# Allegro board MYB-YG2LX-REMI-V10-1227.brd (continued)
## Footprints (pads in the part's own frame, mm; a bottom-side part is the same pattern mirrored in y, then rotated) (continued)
TSSOP16
  oval 1.6x0.27 smd: 1(-2.9,2.275) 2(-2.9,1.625) 3(-2.9,0.975) 4(-2.9,0.325) 5(-2.9,-0.325) 6(-2.9,-0.975) 7(-2.9,-1.625) 8(-2.9,-2.275) 9(2.9,-2.275) 10(2.9,-1.625) 11(2.9,-0.975) 12(2.9,-0.325) 13(2.9,0.325) 14(2.9,0.975) 15(2.9,1.625) 16(2.9,2.275)
TSSOP20
  oval 1.5x0.3 smd: 1(-2.8,2.925) 2(-2.8,2.275) 3(-2.8,1.625) 4(-2.8,0.975) 5(-2.8,0.325) 6(-2.8,-0.325) 7(-2.8,-0.975) 8(-2.8,-1.625) 9(-2.8,-2.275) 10(-2.8,-2.925) 11(2.8,-2.925) 12(2.8,-2.275) 13(2.8,-1.625) 14(2.8,-0.975) 15(2.8,-0.325) 16(2.8,0.325) 17(2.8,0.975) 18(2.8,1.625) 19(2.8,2.275) 20(2.8,2.925)
TYPE-C-BTCF-16-307
  round 0.65 hole 0.65 unplated: (-2.89,3.605) (2.89,3.605)
  oval 0.25x1.15 smd: A1(-3.35,4.67) A4(-2.55,4.67) A5(-1.25,4.67) A6(-0.25,4.67) A7(0.25,4.67) A8(1.25,4.67) A9(2.55,4.67) A12(3.35,4.67) B1(3.05,4.67) B4(2.25,4.67) B5(1.75,4.67) B6(0.75,4.67) B7(-0.75,4.67) B8(-1.75,4.67) B9(-2.25,4.67) B12(-3.05,4.67)
  oval 1.2x1.9 hole 0.7x1.5: SH1(-4.32,-0.075) SH2(4.32,-0.075)
  oval 1.2x2.3 hole 0.7x1.8: SH3(-4.32,4.105) SH4(4.32,4.105)
UB11121-8FDE-4F
  round 3.2 hole 2.2: 1(-6.57,-1.5) 2(-6.57,-7.2) 3(6.57,-7.2) 4(6.57,-1.5)
  round 1.6 hole 0.92: A1(3.5,-6.83) A2(1,-6.83) A3(-1,-6.83) A4(-3.5,-6.83) B1(3.5,-4.21) B2(1,-4.21) B3(-1,-4.21) B4(-3.5,-4.21)
unnamed#2
  round 1.016 smd: 1(0,0)
unnamed#3
  round 3 hole 3 unplated: (0,0)
UT12111-B1609-7F
  round 0.6 hole 0.6 unplated: (-3.4,2) (3.4,2)
  oval 0.25x1.25 smd: A1(-2.62,4.105) A2(-2.12,4.105) A3(-1.62,4.105) A4(-1.12,4.105) A5(-0.62,4.105) A6(-0.12,4.105) A7(0.38,4.105) A8(0.88,4.105) A9(1.38,4.105) A10(1.88,4.105) A11(2.38,4.105) A12(2.88,4.105)
  oval 0.25x1 smd: B1(2.62,2.6) B2(2.12,2.6) B3(1.62,2.6) B4(1.12,2.6) B5(0.62,2.6) B6(0.12,2.6) B7(-0.38,2.6) B8(-0.88,2.6) B9(-1.38,2.6) B10(-1.88,2.6) B11(-2.38,2.6) B12(-2.88,2.6)
  oval 1.6x2.8 hole 0.6x1.8: SH1(-4.32,-1.2) SH2(4.32,-1.2)
  oval 1.5x2.5 hole 0.6x1.6: SH3(-4.32,3.35) SH4(4.32,3.35)
  oval 1.5x0.9 hole 1.2x0.6: SH5(-3.99,2.85) SH6(3.99,2.85)
VSSOP8
  oval 0.9x0.22 smd: 1(-1.5,0.75) 2(-1.5,0.25) 3(-1.5,-0.25) 4(-1.5,-0.75) 5(1.5,-0.75) 6(1.5,-0.25) 7(1.5,0.25) 8(1.5,0.75)
WLCSP10
  round 0.25 smd: A1(-0.6,0.4) A2(-0.2,0.4) A3(0.2,0.4) A4(0.6,0.4) B1(-0.4,0) B2(0.4,0) C1(-0.6,-0.4) C2(-0.2,-0.4) C3(0.2,-0.4) C4(0.6,-0.4)
WLCSP15
  round 0.203 smd: A1(-1,0.4) A2(-0.6,0.4) A3(-0.2,0.4) A4(0.2,0.4) A5(0.6,0.4) A6(1,0.4) B1(-0.8,0) B2(0,0) B3(0.8,0) C1(-1,-0.4) C2(-0.6,-0.4) C3(-0.2,-0.4) C4(0.2,-0.4) C5(0.6,-0.4) C6(1,-0.4)
WQ21801-B2180-7F
  round 1 hole 1 unplated: (-4.85,-3.1) (3.15,-3.1)
  oval 0.7x1.6 smd: 1(2.25,7.9) 2(1.15,7.9) 3(0.05,7.9) 4(-1.05,7.9) 5(-2.15,7.9) 6(-3.25,7.9) 7(-4.35,7.9) 8(-5.45,7.9) 9(-6.55,7.9)
  oval 1.2x1.8 smd: 10(-7.75,6.6)
  oval 1.6x1.5 smd: 11(6.95,6.85)
  oval 1.2x2.2 smd: 12(-7.75,-2.7) 13(7.75,-2.7)

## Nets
GND: C1.2 C2.2 C3.2 C4.2 C5.2 C6.2 C7.2 C8.2 C9.2 C12.2 C13.2 C14.1 C15.2 C16.2 C17.2 C20.2 C21.2 C22.2 C23.2 C25.2 C26.2 C27.2 C28.2 C29.2 C30.2 C31.2 C32.2 C33.2 C34.2 C35.2 C36.2 C37.2 C38.2 C39.2 C40.2 C41.2 C42.2 C44.2 C45.2 C46.2 C47.2 C48.2 C49.2 C50.2 C51.2 C52.2 C53.2 C54.2 C55.1 C56.2 C57.2 C58.2 C59.2 C60.2 C61.2 C62.2 C63.2 C64.2 C65.2 C66.2 C67.2 C68.2 C69.2 C70.2 C71.2 C73.2 C74.2 C75.2 C76.2 C77.2 C78.2 C79.2 C80.2 C81.2 C82.2 C83.2 C84.2 C85.2 C86.2 C87.2 C88.2 C89.2 C90.2 C91.2 C92.2 C93.2 C94.2 C95.2 C96.2 C103.2 C104.2 C109.2 C110.2 C111.2 C112.2 C113.2 C114.2 C115.2 C116.2 C117.2 C118.2 C119.2 C120.2 C121.1 C122.2 C123.2 C124.2 C125.2 C126.2 C127.2 C128.2 C129.2 C130.2 C131.2 C132.2 C133.2 C134.2 C135.2 C136.2 C137.1 C138.2 C139.2 C140.2 C141.2 C142.2 C143.2 C144.2 C145.2 C146.1 C147.2 C148.2 C149.2 C152.2 C153.2 C154.2 C155.2 C156.2 C157.2 C158.2 C159.2 C160.2 C161.2 C162.2 C163.2 C164.2 C165.2 C166.2 C167.2 C168.2 C169.2 C170.2 C171.2 C172.2 C173.2 C174.2 C176.2 C177.2 C178.2 D1.1 D2.1 D3.1 D4.1 D5.1 D6.1 D7.1 D8.1 D9.1 D10.1 D11.1 D12.1 D13.1 D14.1 D15.1 D16.1 D18.1 D19.1 D20.1 D21.1 D22.1 D23.1 D24.1 D30.1 D31.1 D32.1 D33.1 D34.1 D35.1 D37.1 D38.1 D39.2(K) D41.2(K) D43.1 D44.1 D45.1 D46.1 D47.2 J1.A1(GND#A1) J1.A12(GND#A12) J1.B1(GND#B1) J1.B12(GND#B12) J2.8 J2.10 J2.13 J2.16 J2.19 J2.22 J2.25 J2.26 J3.A1(GND1) J3.A12(GND2) J3.B1(GND4) J3.B12(GND3) J4.A4(GND#A4) J4.B4(GND#B4) J5.6(VSS) J5.10(GND) J5.11(SH1) J5.12(SH2) J5.13(SH3) J6.7(GND2) J6.10(GND3) J6.13(GND4) J6.16(GND5) J6.19(GND6) J6.22(GND7) J6.25(GND8) J6.30(GND9) J6.41(AGND) J6.42(GND1) J7.2(SHIELD0) J7.5(SHIELD1) J7.8(SHIELD2) J7.11(SHIELD3) J7.17(GND) J9.12(YELLOW-) J9.14(GREEN-) J10.12(YELLOW-) J10.14(GREEN-) J13.6 J13.9 J13.14 J13.20 J13.25 J13.30 J13.34 J13.39 J14.2 J15.3 J16.3 J17.2(GND1) J17.3(GND) J18.2(GND1) J18.3(GND) MTG5.1 MTG6.1 R4.2 R5.1 R6.1 R9.1 R12.2 R14.2 R18.2 R19.2 R45.2 R48.2 R49.2 R52.2 R53.2 R62.2 R63.2 R64.2 R65.2 R100.1 R104.1 R105.2 R106.2 R120.1 R132.2 R157.2 R158.1 R165.2 R166.2 R167.2 R168.2 R169.2 R170.2 R171.2 R172.2 R173.2 R194.2 R195.1 R202.2 R203.2 R204.2 R205.2 R206.2 R207.2 R208.2 R209.2 R210.2 R222.1 R233.2 R234.2 R243.1 R244.1 R245.1 R246.1 R255.1 R270.1 S1.1 S1.2 S2.1 S2.2 TP2.1(TP) TP5.1(TP) TP6.1(TP) U2.6(NMOS#) U2.14(ISP) U2.15(ISN) U2.21(GND) U3.2(GND) U4.2(GND) U5.B1(GND_CH1) U5.B2(GND_CH2) U6.B1(GND_CH1) U6.B2(GND_CH2) U6.B3(GND_CH3) U7.11(GND) U8.2(GND) U9.10(GND) U9.22(VSYS) U9.25(EP) U10.29(GND29) U11.6(VSSA_MIPIRX) U11.17(VSS#17) U11.23(VSSA_HDMITX#23) U11.29(VSSA_HDMITX#29) U11.32(VSS#32) U11.36(VSSA_HDMIPLL) U11.42(VSSA_LVDSTX) U11.49(VSSA_SYSCLK) U11.51(VSSA_LVDSPLL) U11.56(VSS#56) U11.65(GND_EP) U12.B1(GND_CH1) U12.B2(GND_CH2) U13.B1(GND_CH1) U13.B2(GND_CH2) U14.2(GND) U15.4(DGND) U15.29(EPGND) U16.49(GND) U17.2(GND) U18.2(GND) U19.49(GND) U20.2(GND) U21.2(GND) U22.1(GND#1) U22.3(GND#3) U22.4(GND#4) U22.5(GND#5) U22.6(GND#6) U22.7(GND#7) U22.8(GND#8) U22.10(GND#10) U22.11(GND#11) U22.23(GND#23) U22.32(GND#32) U22.39(GND#39) U23.8(GND) U24.8(GND) U25.4(NC#4) U25.8(NC#8) U25.9(NC#9) U25.11(GND) U25.14(NC#14) U26.14 U26.21 U26.32 U26.39 U26.46 U26.49 U26.52 U26.55 U26.58 U26.61 U26.64 U26.67 U26.70 U26.73 U26.76 U26.79 U26.82 U26.83 U26.101 U26.115 U26.125 U26.138 U26.149 U26.164 U26.L8 U26.L46 Y1.2(GND) Y2.2 Y2.4 Y3.2 Y3.4 Y4.2(GND) Y5.2(GND) Y6.2(GND) Y7.2(GND/NC) Y7.4(GND) Y8.2(GND/NC) Y8.4(GND) Y9.2(GND)
GND_EARTH: C14.2 C55.2 C81.1 J1.SH1 J1.SH2 J1.SH3 J1.SH4 J3.SH1 J3.SH2 J3.SH3 J3.SH4 J3.SH5 J3.SH6 J4.1(BODY1) J4.2(BODY2) J4.3(BODY3) J4.4(BODY4) J7.20(GND0) J7.21(GND3) J7.22(GND1) J7.23(GND2) J9.15(GND1) J9.16(GND2) J10.15(GND1) J10.16(GND2) MTG1.1(GND1) MTG1.2(GND2) MTG1.3(GND3) MTG1.4(GND4) MTG1.5(GND5) MTG1.6(GND6) MTG1.7(GND7) MTG1.8(GND8) MTG1.9(GND9) MTG2.1(GND1) MTG2.2(GND2) MTG2.3(GND3) MTG2.4(GND4) MTG2.5(GND5) MTG2.6(GND6) MTG2.7(GND7) MTG2.8(GND8) MTG2.9(GND9) MTG3.1(GND1) MTG3.2(GND2) MTG3.3(GND3) MTG3.4(GND4) MTG3.5(GND5) MTG3.6(GND6) MTG3.7(GND7) MTG3.8(GND8) MTG3.9(GND9) MTG4.1(GND1) MTG4.2(GND2) MTG4.3(GND3) MTG4.4(GND4) MTG4.5(GND5) MTG4.6(GND6) MTG4.7(GND7) MTG4.8(GND8) MTG4.9(GND9) R4.1 R53.1 R104.2
VDD_1V8: C24.2 C25.1 C26.1 C27.1 C35.1 C36.1 C37.1 C38.1 FB1.2 FB3.2 FB4.2 L3.2 Q5.3(C) R17.2 R26.1 R27.1 R28.1 R29.1 R30.1 R31.1 R34.1 R76.1 R230.1 TP4.1(TP) U7.2(VCCA) U8.3(VCCA)
VDD_3V3: C19.1 C20.1 C21.1 C22.1 C23.1 C33.1 C34.1 C39.1 C40.1 C60.1 C61.1 C62.1 C63.1 C90.1 C103.1 C104.1 C113.1 C114.1 C115.1 C160.1 C161.1 D40.2(NC) FB5.1 FB6.1 FB7.1 FB8.1 FB9.2 FB10.1 FB12.2 FB13.1 FB15.1 J13.1 J13.17 L2.2 Q6.1(G) Q7.1(G) Q8.1(G) Q9.1(G) R11.1 R32.1 R33.1 R39.1 R43.1 R44.1 R46.1 R54.1 R57.2 R67.2 R83.1 R84.1 R85.1 R107.1 R108.1 R115.1 R137.2 R138.2 R156.2 R162.1 R163.1 R164.1 R174.2 R175.2 R193.2 R199.1 R200.1 R201.1 R241.2 R242.2 R247.1 R249.1 R250.1 R254.1 R257.1 R261.1 R263.1 R267.1 TP3.1(TP) U7.19(VCCB) U8.7(VCCB) U10.14(VDD33#14) U10.21(VDD33#21) U10.28(VDD33#28) U14.3(VCCA) U14.6(OE) U15.2(DVDD) U15.3(PVDD) U23.16(VCC) U24.16(VCC)
VDD_5V: C3.1 C4.1 C5.1 C6.1 C7.1 C8.1 C9.1 C15.1 C16.1 C17.1 C28.1 C31.1 C32.1 C41.1 C42.1 C46.1 C56.1 C57.1 C58.1 C59.1 C68.1 C69.1 C91.1 C162.1 C163.1 C172.1 D1.2 D17.1 D25.1 D26.1 D47.1 F1.2 F2.1 F3.2 J2.1 J6.2(VCC5V#2) J6.3(VCC5V#3) J13.2 J13.4 Q3.3(D) R10.1 R16.1 R38.1 R109.1 R110.1 R248.2 R269.1 TP1.1(TP) U3.5(IN) U4.4(VIN) U9.24(VDD) U14.7(VCCB)
VDD_5V_VBUS: C51.1 C52.1 C53.1 C54.1 F2.2 F3.1 J4.A1(VCC#A1) J4.B1(VCC#B1) R55.1 T8.1(TP)
VDD_ADC_VREF: C107.1 R130.2 U15.19(ADCVREF)
VDD_BAT: D40.1(ANODE) J14.1
VDD_BL_3V3: C153.1 C154.1 C155.1 C156.1 FB15.2 R211.2 R212.2 R213.2 R214.2 R215.2 R229.1 R235.2 R236.2 R237.2 R238.2 R239.2 R240.2 U22.34(VDDIO) U22.36(VCC33)
VDD_LDO: C13.1 R3.2 U2.7(VDD)
VDD_PHY0_3V3: C116.1 C117.1 C118.1 FB9.1 R154.1 R155.1 U16.30(DVDD33) U16.31(VDD33_LX)
VDD_PHY1_3V3: C132.1 C133.1 C134.1 FB12.1 R190.1 R191.1 U19.30(DVDD33) U19.31(VDD33_LX)
VDD_RGMII0: C130.1 C131.1 R156.1 R159.1 R160.1 R161.1 U16.29(DVDD_RGMII)
VDD_RGMII1: C147.1 C148.1 R193.1 R196.1 R197.1 R198.1 U19.29(DVDD_RGMII)
VDD_RTC: C165.1 C166.1 C167.1 D40.3(CATHODE) R256.1 U25.6(VDD)
VDD_SD: C66.1 C67.1 J5.4(VCC) R66.1 R67.1 R68.1 R69.1 R70.1 R71.1 R72.1 R73.1 R74.1
VDD_SOM_3V3OUT: C173.1 C174.1 R56.2 R66.2 R253.1 U26.87
VDD_SOM_5VIN: C168.1 C169.1 C170.1 C171.1 R269.2 U26.84 U26.85 U26.86
VDD_USB0_VBUS: C44.1 C45.1 D6.2 FB2.2 J3.A4(VBUS1) J3.A9(VBUS2) J3.B4(VBUS4) J3.B9(VBUS3) R35.2
VDD_VBUS: C1.1 C2.1 J1.A4(VBUS#A4) J1.A9(VBUS#A9) J1.B4(VBUS#B4) J1.B9(VBUS#B9) U1.2 U2.2(VBUS)
VDD_VBUS_5V: F1.1 U1.3
VDDA_AUDIO_3V3: C101.1 C102.1 FB6.2 U15.16(HPVDD) U15.17(AVDD)
VDDA_PHY0_1V1: C125.1 C126.1 C127.1 FB11.2 U16.4(AVDDL#4) U16.9(AVDDL#9) U16.47(AVDDL#47)
VDDA_PHY0_3V3: C119.1 C120.1 FB10.2 U16.1(AVDD33#1) U16.12(AVDD33#12)
VDDA_PHY1_1V1: C143.1 C144.1 C145.1 FB14.2 U19.4(AVDDL#4) U19.9(AVDDL#9) U19.47(AVDDL#47)
VDDA_PHY1_3V3: C135.1 C136.1 FB13.2 U19.1(AVDD33#1) U19.12(AVDD33#12)
VDDL_PHY0_1V1: C122.1 C123.1 C124.1 FB11.1 L6.2 U16.22(DVDDL)
VDDL_PHY1_1V1: C138.1 C139.1 C142.1 FB14.1 L7.2 U19.22(DVDDL)
32.7K_CLK: C158.1 R232.2 R233.1 U22.31(LPO)
AUD_MIC: C105.1 D29.2 J8.5 R129.1 R130.1 R131.1
AUDIO1_LOUT_L: C97.1 D27.2 J8.3 R116.2 R124.1
AUDIO1_LOUT_R: C98.1 D28.2 J8.6 R123.2
AUDIO_AGND: C97.2 C98.2 C101.2 C102.2 C105.2 C106.2 C107.2 C108.2 D27.1 D28.1 D29.1 J8.2 R124.2 R127.2 R128.1 R131.2 R132.1 U15.18(AGND)
AUDIO_MCLK: C94.1 R114.2 U15.1(MCLK)
CARRIER_PWR_ON: R8.1 R15.1 U26.89
CC1: D3.2 J1.A5(CC1) R5.2 U2.11(CC1)
CC2: D2.2 J1.B5(CC2) R6.2 U2.10(CC2)
CSI_CLK_N: J2.18 U6.A2(CH1_IN-)
CSI_CLK_P: J2.17 U6.A1(CH1_IN+)
CSI_DATA0_N: J2.24 U6.A6(CH3_IN-)
CSI_DATA0_P: J2.23 U6.A5(CH3_IN+)
CSI_DATA1_N: J2.21 U6.A4(CH2_IN-)
CSI_DATA1_P: J2.20 U6.A3(CH2_IN+)
CSI_DATA2_N: J2.15 U5.A4(CH2_IN-)
CSI_DATA2_P: J2.14 U5.A3(CH2_IN+)
CSI_DATA3_N: J2.12 U5.A2(CH1_IN-)
CSI_DATA3_P: J2.11 U5.A1(CH1_IN+)
ET0_LED1: R151.2 R163.2 R165.1 U16.36(LED1/CFG_LDO0)
ET0_LED2: R152.2 R164.2 R166.1 U16.37(LED2/CFG_LDO1)
ET0_LINKSTA: R117.1 U26.L1
ET0_MDC: R137.1 T14.1(TP) U16.14(MDC) U26.22
ET0_MDIO: R138.1 U16.15(MDIO) U26.23
ET0_PHYAD0: R162.2 R173.1 U16.35(LED0/PHYAD0)
ET0_RX_CTL: R146.2 R160.2 R171.1 U26.16
ET0_RXC: R145.2 R161.2 R172.1 U26.15
ET0_RXD0: R147.2 R159.2 R170.1 U26.17
ET0_RXD1: R148.2 R169.1 U26.18
ET0_RXD2: R149.2 R168.1 U26.19
ET0_RXD3: R150.2 R167.1 U26.20
ET0_TRN0: J9.2(TD1-) U16.3(TRXN0) U17.6(D1-)
ET0_TRN1: J9.4(TD2-) U16.6(TRXN1) U17.4(D2-)
ET0_TRN2: J9.8(TD3-) U16.8(TRXN2) U18.6(D1-)
ET0_TRN3: J9.10(TD4-) U16.11(TRXN3) U18.4(D2-)
ET0_TRP0: J9.1(TD1+) U16.2(TPXP0) U17.1(D1+)
ET0_TRP1: J9.3(TD2+) U16.5(TRXP1) U17.3(D2+)
ET0_TRP2: J9.7(TD3+) U16.7(TRXP2) U18.1(D1+)
ET0_TRP3: J9.9(TD4+) U16.10(TRXP3) U18.3(D2+)
ET0_TX_CTL: R141.2 U26.12
ET0_TXC: R140.2 U26.11
ET0_TXD0: R142.2 U26.13
ET0_TXD1: R143.2 U26.10
ET0_TXD2: R144.2 U26.8
ET0_TXD3: R139.2 U26.9
ET1_LED1: R188.2 R200.2 R202.1 U19.36(LED1/CFG_LDO0)
ET1_LED2: R189.2 R201.2 R203.1 U19.37(LED2/CFG_LDO1)
ET1_LINKSTA: U26.L58
ET1_MDC: R174.1 T16.1(TP) U19.14(MDC) U26.24
ET1_MDIO: R175.1 U19.15(MDIO) U26.25
ET1_PHYAD0: R199.2 R210.1 U19.35(LED0/PHYAD0)
ET1_RX_CTL: R183.2 R197.2 R208.1 U26.33
ET1_RXC: R182.2 R198.2 R209.1 U26.34
ET1_RXD0: R184.2 R196.2 R207.1 U26.38
ET1_RXD1: R185.2 R206.1 U26.37
ET1_RXD2: R186.2 R205.1 U26.36
ET1_RXD3: R187.2 R204.1 U26.35
ET1_TRN0: J10.2(TD1-) U19.3(TRXN0) U20.6(D1-)
ET1_TRN1: J10.4(TD2-) U19.6(TRXN1) U20.4(D2-)
ET1_TRN2: J10.8(TD3-) U19.8(TRXN2) U21.6(D1-)
ET1_TRN3: J10.10(TD4-) U19.11(TRXN3) U21.4(D2-)
ET1_TRP0: J10.1(TD1+) U19.2(TPXP0) U20.1(D1+)
ET1_TRP1: J10.3(TD2+) U19.5(TRXP1) U20.3(D2+)
ET1_TRP2: J10.7(TD3+) U19.7(TRXP2) U21.1(D1+)
ET1_TRP3: J10.9(TD4+) U19.10(TRXP3) U21.3(D2+)
ET1_TX_CTL: R180.2 U26.26
ET1_TXC: R176.2 U26.31
ET1_TXD0: R177.2 U26.30
ET1_TXD1: R181.2 U26.29
ET1_TXD2: R178.2 U26.28
ET1_TXD3: R179.2 U26.27
HOST1_USB_DM: L5.2 U10.3(DM1)
HOST1_USB_DP: L5.3 U10.4(DP1)
HOST2_USB_DM: L4.2 U10.6(DM2)
HOST2_USB_DP: L4.3 U10.7(DP2)
HPD_DET: J7.19(HOTPLUG) R103.1 R106.1
HPGND: R127.1 U15.13(HPGND)
INT: R80.2 U11.63(INT)
JTAG_TCK_1V8: U26.L13
JTAG_TDI_1V8: U26.L15
JTAG_TDO_1V8: U26.L11
JTAG_TMS_1V8: U26.L12
JTAG_TRST_N_1V8: U26.L14
LT8912_VCCA_HDMIPLL: C72.2 C82.1 C83.1 C84.1 C85.1 C88.1 C89.1 FB4.1 U11.34(VCCA_HDMIPLL) U11.50(VCCA_SYSCLK) U11.52(VCCA_LVDSPLL)
LT8912_VCCA_HDMITX: C73.1 C74.1 C75.1 C76.1 C77.1 C78.1 C79.1 C80.1 C86.1 C87.1 FB3.1 U11.5(VCCA_MIPIRX) U11.18(VDD#18) U11.26(VCCA_HDMITX) U11.33(VDD#33) U11.41(VCCA_LVDSTX) U11.57(VDD#57)
LVDS_CLK+: J6.18(RXCLK+) U11.39(LVDSTX_CKP)
LVDS_CLK-: J6.17(RXXLK-) U11.40(LVDSTX_CKN)
LVDS_D0+: J6.9(RXIN0+) U11.47(LVDSTX0_DP)
LVDS_D0-: J6.8(RXIN0-) U11.48(LVDSTX0_DN)
LVDS_D1+: J6.12(RXIN1+) U11.45(LVDSTX1_DP)
LVDS_D1-: J6.11(RXIN1-) U11.46(LVDSTX1_DN)
LVDS_D2+: J6.15(RXIN2+) U11.43(LVDSTX2_DP)
LVDS_D2-: J6.14(RXIN2-) U11.44(LVDSTX2_DN)
LVDS_D3+: J6.21(RXIN3+) U11.37(LVDSTX3_DP)
LVDS_D3-: J6.20(RXIN3-) U11.38(LVDSTX3_DN)
OVCUR#: R55.2 T22.1(TP) U10.24(OVCUR2#) U10.25(OVCUR1#)
POWER_ONOFF: R248.1 U26.90
PWREN#: R270.2 U10.8(PWREN#)
RESERVED0: U16.43(RESERVED1)
RESERVED1: U19.43(RESERVED1)
RESET#: R54.2 U10.17(RESET#/CDP)
RESET_IN_N: D36.1 U26.88
RIIC0_SCL_1V8: R25.1 R28.2 R79.1 T4.1(TP) U7.3(A2)
RIIC0_SDA_1V8: R24.1 R27.2 R78.1 T2.1(TP) U7.1(A1)
RIIC1_SCL_5V: J7.15(SCL) R102.2 R109.2 U14.8(B1)
RIIC1_SDA_5V: J7.16(SDA) R101.2 R110.2 U14.1(B2)
RTC_CLK: T19.1(TP) U25.3(FOUT)
RZ_ADC_CH0: U26.L50
RZ_ADC_CH1: U26.L49
RZ_ADC_CH2: U26.L48
RZ_ADC_CH3: U26.L47
RZ_ADC_CH4: U26.L54
RZ_ADC_CH5: U26.L53
RZ_ADC_CH6: U26.L52
RZ_ADC_CH7: U26.L51
RZ_AUDIO_CLK_11_2896M: R134.2 U26.139
RZ_AUDIO_CLK_12_2880M: R136.2 U26.140
RZ_CAN1_RX: J13.16 U26.116
RZ_CAN1_TX: J13.18 U26.117
RZ_CSI_CLK_N: U6.C2(CH1_OUT-) U26.54
RZ_CSI_CLK_P: U6.C1(CH1_OUT+) U26.53
RZ_CSI_DATA0_N: U6.C6(CH3_OUT-) U26.63
RZ_CSI_DATA0_P: U6.C5(CH3_OUT+) U26.62
RZ_CSI_DATA1_N: U6.C4(CH2_OUT-) U26.60
RZ_CSI_DATA1_P: U6.C3(CH2_OUT+) U26.59
RZ_CSI_DATA2_N: U5.C4(CH2_OUT-) U26.66
RZ_CSI_DATA2_P: U5.C3(CH2_OUT+) U26.65
RZ_CSI_DATA3_N: U5.C2(CH1_OUT-) U26.57
RZ_CSI_DATA3_P: U5.C1(CH1_OUT+) U26.56
RZ_DEBUGEN: SW1.5(ON4) U26.141
RZ_DISP_CLK: U26.L43
RZ_DISP_DATA0: R212.1 U22.44(SD RESET) U26.L17
RZ_DISP_DATA1: R213.1 U22.38(BT_REG_ON) U26.L18
RZ_DISP_DATA2: U26.L19
RZ_DISP_DATA3: R216.2 U26.L20
RZ_DISP_DATA4: R217.2 U26.L21
RZ_DISP_DATA5: U26.L22
RZ_DISP_DATA6: R242.1 R246.2 U23.1(S) U26.L23
RZ_DISP_DATA7: R245.2 U23.15(NOE) U26.L24
RZ_DISP_DATA8: R241.1 R244.2 U24.1(S) U26.L25
RZ_DISP_DATA9: R243.2 U24.15(NOE) U26.L26
RZ_DISP_DATA10: U26.L27
RZ_DISP_DATA11: U26.L28
RZ_DISP_DATA12: U26.L30
RZ_DISP_DATA13: U26.L31
RZ_DISP_DATA14: U26.L32
RZ_DISP_DATA15: U26.L33
RZ_DISP_DATA16: U26.L34
RZ_DISP_DATA17: U26.L35
RZ_DISP_DATA18: U26.L36
RZ_DISP_DATA19: U26.L37
RZ_DISP_DATA20: U7.12(B8) U26.L38
RZ_DISP_DATA21: U26.L39
RZ_DISP_DATA22: R215.1 U22.16(WL_WAKE_HOST) U26.L40
RZ_DISP_DATA23: R214.1 U22.50(BT_WAKE_HOST) U26.L41
RZ_DISP_DE: U26.L44
RZ_DISP_HSYNC: U26.L42
RZ_DISP_VSYNC: U26.L45
RZ_DSI_CLK_N: R95.2 U26.81
RZ_DSI_CLK_P: R93.2 U26.80
RZ_DSI_DATA0_N: R82.2 U26.72
RZ_DSI_DATA0_P: R88.2 U26.71
RZ_DSI_DATA1_N: R90.2 U26.75
RZ_DSI_DATA1_P: R89.2 U26.74
RZ_DSI_DATA2_N: R97.2 U26.69
RZ_DSI_DATA2_P: R96.2 U26.68
RZ_DSI_DATA3_N: R99.2 U26.78
RZ_DSI_DATA3_P: R98.2 U26.77
RZ_MD_BOOT0: SW1.8(ON1) U26.156
RZ_MD_BOOT1: R64.1 SW1.7(ON2) U26.158
RZ_MD_BOOT2: R65.1 SW1.6(ON3) U26.157
RZ_P1_0_USER_KEY: C164.1 D38.2 R247.2 S2.3 S2.4 U26.100
RZ_P1_1: R43.2 U9.9(ALERT#) U26.L57
RZ_P4_1: J13.13 U26.L16
RZ_P16_1_1V8: R76.2 R80.1 U7.9(A8)
RZ_P22_1_ETH0: J13.7 U26.L3
RZ_P23_0_ETH0: J13.15 U26.L4
RZ_P23_1_ETH0: J13.29 U26.L2
RZ_P27_0_ETH0: J13.31 U26.L5
RZ_P32_0_ETH1: J13.22 U26.L7
RZ_P32_1_ETH1: J13.12 U26.L10
RZ_P33_0_ETH1: J13.26 U26.L6
RZ_P36_1_ETH1: J13.32 U26.L9
RZ_P39_0: U7.17(B3) U26.129
RZ_P39_0_1V8: R23.1 R29.2 U7.4(A3)
RZ_P39_1: U7.16(B4) U26.97
RZ_P39_1_1V8: J2.6 R30.2 U7.5(A4)
RZ_P39_2: U7.15(B5) U26.102
RZ_P39_2_1V8: J2.7 R31.2 U7.6(A5)
RZ_P40_2: J13.11 U26.98
RZ_P42_2: U7.14(B6) U26.43
RZ_P42_2_1V8: R81.1 U7.7(A6)
RZ_P42_3: R84.2 R87.1 U26.44
RZ_P42_4: J13.36 U26.41
RZ_P43_0: R83.2 R86.1 U26.99
RZ_P43_1: D42.2(K) U26.95
RZ_P43_2: R190.2 U19.34(INT_N/PME_N) U26.91
RZ_P43_3: R191.2 R194.1 U19.13(RESET_N) U26.94
RZ_P44_2: R154.2 U16.34(INT_N/PME_N) U26.92
RZ_P44_3: R155.2 R157.1 U16.13(RESET_N) U26.96
RZ_P48_2: R85.2 R94.1 U26.93
RZ_PRST_N: U26.40
RZ_QSPI0_IO0: U26.155
RZ_QSPI0_IO1: U26.151
RZ_QSPI0_IO2: U26.154
RZ_QSPI0_IO3: U26.153
RZ_QSPI0_SPCLK: U26.150
RZ_QSPI0_SSL: U26.152
RZ_QSPI1_INT_N: U26.147
RZ_QSPI1_IO0: U26.145
RZ_QSPI1_IO1: U26.144
RZ_QSPI1_IO2: U26.146
RZ_QSPI1_IO3: U26.143
RZ_QSPI1_SPCLK: U26.148
RZ_QSPI1_SSL: U26.142
RZ_QSPI_RESET_N: U26.160
RZ_QSPI_WP_N: U26.159
RZ_RIIC0_SCL: R33.2 R44.2 R51.2 R92.1 T3.1(TP) U7.18(B2) U26.104
RZ_RIIC0_SDA: R32.2 R46.2 R50.2 R91.1 T1.1(TP) U7.20(B1) U26.103
RZ_RIIC1_SCL: R108.2 R111.1 R118.1 R251.1 U26.106
RZ_RIIC1_SDA: R107.2 R112.1 R119.1 R252.1 U26.105
RZ_RIIC2_SCL: J13.5 U26.L55
RZ_RIIC2_SDA: J13.3 U26.L56
RZ_RIIC3_SCL: J13.28 U26.162
RZ_RIIC3_SDA: J13.27 U26.161
RZ_RSPI0_CK: J13.23 U26.113
RZ_RSPI0_MISO: J13.21 U26.111
RZ_RSPI0_MOSI: J13.19 U26.112
RZ_RSPI0_SSL: J13.24 U26.114
RZ_SCIF0_RXD: Q6.2(S) R257.2 R259.2 U26.123
RZ_SCIF0_TXD: Q7.2(S) R261.2 R262.2 U26.122
RZ_SCIF1_CTS: R220.2 U26.119
RZ_SCIF1_RTS: R221.2 U26.118
RZ_SCIF1_RXD: R218.2 U26.120
RZ_SCIF1_TXD: R219.2 U26.121
RZ_SCIF2_CTS: J13.35 U26.110
RZ_SCIF2_RTS: U26.109
RZ_SCIF2_RXD: J13.40 U26.107
RZ_SCIF2_TXD: J13.37 U26.108
RZ_SCIF3_RXD: Q8.2(S) R263.2 R265.2 U26.131
RZ_SCIF3_TXD: Q9.2(S) R267.2 R268.2 U26.130
RZ_SCIF4_RXD: J13.10 U26.127
RZ_SCIF4_TXD: J13.8 U26.128
RZ_SD1_CD_N: D24.2 J5.9(CD) R74.2 T13.1(TP) U26.3
RZ_SD1_CLK: U24.7(2A) U26.2
RZ_SD1_CMD: U24.4(1A) U26.6
RZ_SD1_D0: U23.4(1A) U26.4
RZ_SD1_D1: U23.7(2A) U26.1
RZ_SD1_D2: U23.9(3A) U26.7
RZ_SD1_D3: U23.12(4A) U26.5
RZ_SD1_WP_N: J13.38 U26.163
RZ_SSI0_BCK: R121.1 U26.136
RZ_SSI0_RCK: R122.1 U26.135
RZ_SSI0_RXD: R126.1 U26.137
RZ_SSI0_TXD: R125.1 U26.134
RZ_SSI1_BCK: U8.1(B2) U26.132
RZ_SSI1_BCK_1V8: U8.4(A2) U11.60(SCLK_I)
RZ_SSI1_RCK: U8.8(B1) U26.133
RZ_SSI1_RCK_1V8: U8.5(A1) U11.59(WS_I/SPDIF_IN)
RZ_SSI1_RXD: J13.33 U26.124
RZ_SSI1_TXD: U7.13(B7) U26.126
RZ_SSI1_TXD_1V8: U7.8(A7) U11.58(SD0_CEC)
RZ_USB0_DM: D7.2 J3.A7(DN1) J3.B7(DN2) U26.51
RZ_USB0_DP: D8.2 J3.A6(DP1) J3.B6(DP2) U26.50
RZ_USB0_OTG_ID: R39.2 R48.1 T5.1(TP) U26.45
RZ_USB0_VBUSIN: R35.1 U26.42
RZ_USB1_DM: D15.2 U10.1(DMU) U26.48
RZ_USB1_DP: D16.2 U10.2(DPU) U26.47
SD1_CLK: R75.1 T11.1(TP) U24.5(2B1)
SD1_CMD: D20.2 J5.3(CMD) R70.2 T10.1(TP) U24.2(1B1)
SD1_D0: D22.2 J5.7(DAT0) R72.2 T12.1(TP) U23.2(1B1)
SD1_D1: D23.2 J5.8(DAT1) R73.2 U23.5(2B1)
SD1_D2: D18.2 J5.1(DAT2) R68.2 U23.11(3B1)
SD1_D3: D19.2 J5.2(DAT3) R69.2 T9.1(TP) U23.14(4B1)
SDIO_CLK: R223.1 R235.1 U22.18(SDIO_CLK)
SDIO_CMD: R224.1 R236.1 U22.17(SDIO_CMD)
SDIO_DATA0: R225.1 R237.1 U22.21(SDIO_CDATA_0)
SDIO_DATA1: R226.1 R238.1 U22.22(SDIO_CDATA_1)
SDIO_DATA2: R227.1 R239.1 U22.20(SDIO_CDATA_2)
SDIO_DATA3: R228.1 R240.1 U22.19(SDIO_CDATA_3)
TX0_DN: U11.24(HDMITX0_DN) U13.C2(CH1_OUT-)
TX0_DN_OUT: J7.9(D0-) U13.A2(CH1_IN-)
TX0_DP: U11.25(HDMITX0_DP) U13.C1(CH1_OUT+)
TX0_DP_OUT: J7.7(D0+) U13.A1(CH1_IN+)
TX1_DN: U11.27(HDMITX1_DN) U12.C4(CH2_OUT-)
TX1_DN_OUT: J7.6(D1-) U12.A4(CH2_IN-)
TX1_DP: U11.28(HDMITX1_DP) U12.C3(CH2_OUT+)
TX1_DP_OUT: J7.4(D1+) U12.A3(CH2_IN+)
TX2_DN: U11.30(HDMITX2_DN) U12.C2(CH1_OUT-)
TX2_DN_OUT: J7.3(D2-) U12.A2(CH1_IN-)
TX2_DP: U11.31(HDMITX2_DP) U12.C1(CH1_OUT+)
TX2_DP_OUT: J7.1(D2+) U12.A1(CH1_IN+)
TX_CKN: U11.21(HDMITX_CKN) U13.C4(CH2_OUT-)
TX_CKN_OUT: J7.12(CLK-) U13.A4(CH2_IN-)
TX_CKP: U11.22(HDMITX_CKP) U13.C3(CH2_OUT+)
TX_CKP_OUT: J7.10(CLK+) U13.A3(CH2_IN+)
TX_HPD: Q5.2(E) R105.1 U11.14(HPD_CBUS)
UART_CTS: R220.1 R222.2 U22.42(UART_RTS_N)
UART_RTS: R221.1 U22.43(UART_CTS_N)
USB2CC1: C47.1 R40.2 R41.1 U9.2(CC1)
USB2CC2: C48.1 R42.1 R47.2 U9.4(CC2)
WIFI_SD1_CLK: R223.2 U24.6(2B2)
WIFI_SD1_CMD: R224.2 U24.3(1B2)
WIFI_SD1_D0: R225.2 U23.3(1B2)
WIFI_SD1_D1: R226.2 U23.6(2B2)
WIFI_SD1_D2: R227.2 U23.10(3B2)
WIFI_SD1_D3: R228.2 U23.13(4B2)
N23563869: J2.4 R24.2
N23563890: J2.5 R25.2
N23565746: J2.2 R23.2
N23602849: C159.1 D36.2 D37.2 S1.3 S1.4
N23725979: C29.1 FB1.1 R20.1 Y1.4(VCC/VDD)
N23726017: R21.1 Y1.3(OUT/OUTPUT)
N23737816: J2.9 R21.2
N23945057: D39.1(A) R250.2
N23945063: D42.1(A) R254.2
N23950761: R255.2 R256.2 U25.7(FOE)
N23950837: R252.2 U25.13(SDA)
N23950839: R251.2 U25.2(SCL)
N24039867: R26.2 U7.10(OE)
N24681904: D26.2 R101.1 R102.1
N24681967: D25.2 J7.18(+5V)
N24681971: Q5.1(B) R103.2
N24683528: R111.2 U14.5(A1)
N24683530: R112.2 U14.4(A2)
N24696102: R147.1 U16.26(RXD0/RXDLY)
N24696119: R150.1 U16.23(RXD3/CFG_MODE2)
N24696121: R149.1 U16.24(RXD2/CFG_MODE1)
N24696123: R148.1 U16.25(RXD1/CFG_MODE0)
N24696137: R145.1 U16.28(RX_CLK/PHYAD1)
N24696177: C121.2 R153.1 U16.45(XTAL_I) Y7.3
N24696297: C128.1 R153.2 U16.46(XTAL_O) Y7.1
N24696307: R158.2 U16.48(RBIAS)
N24696859: R142.1 U16.19(TXD0)
N24696861: R140.1 T15.1(TP) U16.21(TX_CLK)
N24696875: R143.1 U16.18(TXD1)
N24696881: R139.1 U16.16(TXD3)
N24696883: R144.1 U16.17(TXD2)
N24697239: L6.1 U16.32(LX)
N24759045: R60.2 SW1.3(OFF3)
N24759067: R58.2 R62.1 SW1.1(OFF1)
N24759190: R59.2 SW1.2(OFF2)
N24761427: R56.1 R57.1 R58.1 R59.1 R60.1 R61.1
N24775120: D30.2 J9.11(YELLOW+) R151.1
N24775122: D31.2 J9.13(GREEN+) R152.1
N24775176: C129.1 J9.5(CT1) J9.6(CT2)
N24790962: R141.1 U16.20(TX_CTL)
N24791040: R146.1 U16.27(RX_CTL/PHYAD2)
N24806528: C137.2 R192.1 U19.45(XTAL_I) Y8.3
N24806541: C146.2 R192.2 U19.46(XTAL_O) Y8.1
N24806543: R195.2 U19.48(RBIAS)
N24806599: L7.1 U19.32(LX)
N24806654: D32.2 J10.11(YELLOW+) R188.1
N24806656: D33.2 J10.13(GREEN+) R189.1
N24806876: C140.1 J10.5(CT1)
N24806931: R180.1 U19.20(TX_CTL)
N24806933: R183.1 U19.27(RX_CTL/PHYAD2)
N24807160: R184.1 U19.26(RXD0/RXDLY)
N24807177: R187.1 U19.23(RXD3/CFG_MODE2)
N24807179: R186.1 U19.24(RXD2/CFG_MODE1)
N24807181: R185.1 U19.25(RXD1/CFG_MODE0)
N24807187: R182.1 T18.1(TP) U19.28(RX_CLK/PHYAD1)
N24807847: R177.1 U19.19(TXD0)
N24807849: R176.1 T17.1(TP) U19.21(TX_CLK)
N24807859: R181.1 U19.18(TXD1)
N24807877: R179.1 U19.16(TXD3)
N24807879: R178.1 U19.17(TXD2)
N24944194: D21.2 J5.5(CLK) R71.2 R75.2
N25256263: C141.1 J10.6(CT2)
N25318172: C70.1 R77.1 U11.54(XTALO) Y3.3
N25318239: C71.1 R77.2 U11.53(XTALI) Y3.1
N25318297: R78.2 U11.61(S_SDA)
N25318324: R79.2 U11.62(S_SCL)
N25318354: R81.2 U11.64(RESET_N)
N25318494: R88.1 U11.1(MIPIRX0_DP)
N25318514: R82.1 U11.2(MIPIRX0_DN)
N25318534: R89.1 U11.3(MIPIRX1_DP)
N25318541: R90.1 U11.4(MIPIRX1_DN)
N25318586: R93.1 U11.7(MIPIRX_CKP)
N25318611: R95.1 U11.8(MIPIRX_CKN)
N25318630: R96.1 U11.9(MIPIRX2_DP)
N25318650: R97.1 U11.10(MIPIRX2_DN)
N25318670: R98.1 U11.11(MIPIRX3_DP)
N25318677: R99.1 U11.12(MIPIRX3_DN)
N25318682: R100.2 U11.13(R6K)
N25318705: C72.1 U11.35(LPF)
N25392814: D41.1(A) R253.2
N25530830: C111.1 C112.1 FB8.2 R135.1 Y6.4(VCC)
N25530834: R135.2 Y6.1(EN)
N25530860: R136.1 Y6.3(OUT)
N25531113: C109.1 C110.1 FB7.2 R133.1 Y5.4(VCC)
N25531117: R133.2 Y5.1(EN)
N25531143: R134.1 Y5.3(OUT)
N25776699: C30.1 R20.2 Y1.1(EN/VCONT/NC)
N25785637: R61.2 R63.1 SW1.4(OFF4)
N25800737: R249.2 U25.10(NINT)
N25931049: J6.27(BL_CTR) R86.2
N25931053: J6.33(TP_MOSI) R91.2
N25931055: J6.34(TP_SCK) R92.2
N25931057: J6.36(TP_PEN) R94.2
N25931062: J6.28(TP_CS) R87.2
N25991714: D5.2 J1.A6(DP1) J1.B6(DP2) U2.8(UDP)
N25991722: D4.2 J1.A7(DN1) J1.B7(DN2) U2.9(UDM)
N26002192: R3.1 R9.2 U2.1(DRV) U2.19(CFG1)
N26033210: C12.1 R10.2 R12.1 R15.2 U3.4(EN)
N26033282: C18.2 L2.1 U3.6(LX)
N26033286: C18.1 U3.1(BS)
N26033313: C19.2 R11.2 R14.1 U3.3(FB)
N26043102: C24.1 R17.1 R19.1 U4.5(FB)
N26043137: L3.1 U4.3(LX)
N26043190: C178.1 R8.2 R16.2 R18.1 U4.1(EN)
N26044739: R234.1 U22.46(NC9) U22.48(NC11)
N26044834: C149.1 C150.2 D34.2 J18.1(SIG)
N26044878: C151.2 C152.1 D35.2 J17.1(SIG)
N26044892: C150.1 U22.9(RF0)
N26044934: R211.1 R217.1 U22.15(WL_REG_ON)
N26045129: R219.1 U22.41(UART_RXD)
N26045131: R218.1 U22.40(UART_TXD)
N26045353: R231.2 Y9.1(EN/VCONT/NC)
N26045371: C157.1 R229.2 R230.2 R231.1 Y9.4(VCC/VDD)
N26045413: R232.1 Y9.3(OUT/OUTPUT)
N26045441: R216.1 U22.49(HOST_WAKE_BT)
N26045646: C151.1 U22.2(RF1)
N26048215: CT2.1 U15.11(ROUT1)
N26048218: CT1.1 U15.12(LOUT1)
N26048225: R121.2 U15.5(SCLK)
N26048227: R122.2 U15.7(LRCK)
N26048236: C96.1 R119.2 U15.27(CDATA)
N26048238: C95.1 R118.2 U15.28(CCLK)
N26048526: R115.2 R117.2 R120.2 U15.26(CE)
N26048542: C108.1 U15.20(VMID)
N26048550: C106.1 U15.10(VREF)
N26048576: C100.1 R129.2
N26048711: R126.2 U15.8(ASDOUT)
N26048728: R125.2 U15.6(DSDIN)
N26048948: C99.2 U15.23(RIN1)
N26048966: C99.1 R128.2
N26049021: C100.2 U15.24(LIN1)
N26049089: CT1.2 R116.1
N26049137: CT2.2 R123.1
N26059117: C43.1 Q3.1(G) Q4.1(G) R36.2 R37.1
N26059354: D9.2 J3.A5(CC1) R41.2
N26059364: D10.2 J3.B5(CC2) R42.2
N26059408: R51.1 U9.7(SCL)
N26059410: R50.1 U9.8(SDA)
N26059424: C50.1 U9.23(VREG_2V7)
N26059430: R47.1 U9.5(CC2DB)
N26059432: R40.1 U9.1(CC1DB)
N26059441: C43.2 Q3.2(S) Q4.2(S) R36.1
N26059484: C49.1 U9.21(VREG_1V2)
N26059520: R52.1 U9.6(RESET)
N26059554: R38.2 R45.1 U9.3(VCONN)
N26059572: R37.2 U9.20(VBUS_EN_SRC)
N26059598: FB2.1 Q4.3(D) U9.18(VBUS_SENSE)
N26059749: R49.1 U9.13(ADDR0)
N26081452: C92.1 C93.1 FB5.2 R113.1 Y4.4(VCC)
N26081456: R113.2 Y4.1(EN)
N26081482: R114.1 Y4.3(OUT)
N26098482: D44.2 J15.2 R260.2
N26098494: D43.2 J15.1 R258.2
N26098528: Q6.3(D) R258.1 R259.1
N26098578: Q7.3(D) R260.1 R262.1
N26103216: D46.2 J16.2 R266.2
N26103218: D45.2 J16.1 R264.2
N26103260: Q8.3(D) R264.1 R265.1
N26103310: Q9.3(D) R266.1 R268.1
N26112798: R34.2 U8.6(OE)
N26137432: C176.1 C177.1 D17.2 U10.27(V5)
N26147104: C64.1 U10.10(XI) Y2.3
N26147108: C65.1 U10.11(XO) Y2.1
N26155524: D11.2 J4.A2(USBHMA) L4.1
N26155536: D12.2 J4.A3(USBHPA) L4.4
N26155544: D14.2 J4.B2(USBHMB) L5.1
N26155546: D13.2 J4.B3(USBHPB) L5.4
N26211804: T20.1(TP) U2.13(CFG2)
N26211815: T21.1(TP) U2.12(CFG3)
N2605947810: T6.1(TP) U9.11(VBUS_VALID)
N2605947811: T7.1(TP) U9.12(ATTACH)

Pads without a net: J1 A8 B8; J2 3; J3 A2 A3 A8 A10 A11 B2 B3 B8 B10 B11; J6 1 4 5 6 23 24 26 29 31 32 35 37 38 39 40; J7 13 14; J8 4 7; M1 1; M2 1; M3 1; M4 1; M5 1; M6 1; REF 1; REF#2 1; TEMPLATE1 1; U1 1; U2 3 4 5 16 17 18 20; U9 14 15 16 17 19; U10 5 9 12 13 15 16 18 19 20 22 23 26; U11 15 16 19 20 55; U15 9 14 15 21 22 25; U16 33 38 39 40 41 42 44; U17 5; U18 5; U19 33 38 39 40 41 42 44; U20 5; U21 5; U22 12 13 14 24 25 26 27 28 29 30 33 35 37 45 47; U24 9 10 11 12 13 14; U25 1 5 12; U26 L29

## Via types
v1: diameter 0.406, hole 0.203, TOP to BOTTOM, 1472 vias

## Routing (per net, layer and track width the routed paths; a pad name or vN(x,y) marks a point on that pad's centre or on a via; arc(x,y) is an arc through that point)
GND: length 867.8
  TOP w0.152: v1(22.02,43.43) 21.79,43.66 20.49,43.66 19.86,44.3 19.86,45.87 19.63,46.1 19.17,46.1 18.74,46.53 v1(18.74,46.89) 18.54,47.09 18.54,51.54 17.55,52.53 15.9,52.53 15.64,52.78 15.64,53.24 15.87,53.47 ; 15.87,53.47 15.67,53.67 15.67,54.69 v1(15.4,54.95) ; 15.87,53.47 17.57,53.47 v1(19.73,51.31) 20.04,51 20.04,47.97 v1(20.21,47.79) 19.71,47.28 19.71,47.04 20.19,46.56 20.87,46.56 21.64,45.8 21.64,44.55 21.89,44.3 22.42,44.3 23.14,43.59 v1(23.8,43.59) ; C12.2 30.21,43.55 32.33,45.67 32.33,48.08 v1(32.53,48.29) ; v1(29.33,43.56) 29.33,43.87 31.67,46.2 31.67,49.43 31.44,49.66 31.06,49.66 30.72,49.32 v1(30.72,48.5)
  TOP w0.203: v1(23.41,26.95) 24.38,27.92 U11.17 ; v1(19.35,24.92) 18.75,24.32 U11.42 ; v1(19.35,26.95) 19.58,27.18 U11.29 ; v1(21.38,22.89) 21.18,22.69 U11.56 ; U11.49 v1(17.19,21.17) ; U11.32 18.38,29.82 v1(17.9,30.3) ; v1(23.41,23.9) 23.43,23.92 U11.6 ; v1(22.4,26.95) 21.98,27.37 U11.23 ; U11.36 18.57,26.72 v1(19.35,25.93)
  TOP w0.254: v1(22.42,18.87) 22.37,18.82 21.48,18.82 20.87,19.43 20.87,20.29 v1(20.93,20.35) 21.18,20.6 U11.56 ; J7.11 v1(19.63,8.48) ; 61.74,8.61 62.53,7.82 J1.A1 ; 61.74,8.61 62.12,8.61 62.83,7.9 J1.B12 ; 61.74,8.61 61.18,8.61 ; U7.11 v1(26.31,31.47) ; v1(13.46,51.64) 13.31,51.79 U6.B1 U6.B2 U6.B3 13.31,54.86 v1(13.09,55.08) ; J6.30 v1(9.88,30.62) ; J7.2 v1(24.13,8.48) ; v1(22.24,13.34) U12.B2 U12.B1 v1(24.1,13.34) ; J3.A1 77.61,6.35 77.35,6.09 J3.B12 ; v1(19.43,13.34) U13.B2 U13.B1 v1(21.28,13.34) ; 18.46,15.39 v1(17.67,15.39) ; 18.46,15.39 18.46,14.55 v1(18.41,14.5) ; 18.46,15.39 18.97,15.39 19.17,15.6 20.26,15.6 Y3.2 ; C95.2 36.48,24.46 C94.2 ; U5.B1 v1(13.31,48.75) ; J7.17 v1(16.63,8.47) ; J7.8 v1(21.13,8.48) ; J2.19 v1(8.93,52.42) ; J7.5 v1(22.63,8.48) ; U26.14 87.54,26.18 v1(87.37,26.01) ; v1(8.25,48.46) 8.8,47.92 J2.10 ; J2.16 v1(8.93,50.92) ; J1.A12 69.23,7.82 70.02,8.61 ; J6.19 v1(12.65,25.12) ; 70.02,8.61 70.58,8.61 ; 70.02,8.61 69.64,8.61 68.93,7.9 J1.B1 ; U5.B2 v1(13.31,50.93) ; R157.2 v1(99.16,23.8) ; J2.13 v1(8.93,49.42) ; J6.7 v1(12.65,19.12) ; 83.44,8.03 83.11,7.71 J3.A12 83.11,6.39 82.85,6.12 J3.B1 ; U11.51 v1(19.18,20.22) 19.1,20.22 18.63,19.75 v1(18.63,19.02) ; J6.25 v1(12.65,28.12) ; J2.22 v1(8.93,53.92) ; J2.8 8.76,46.92 v1(8.28,46.43) ; U15.4 v1(36.81,20.83)
  TOP w0.305: J6.10 v1(12.65,20.62) ; U24.8 32.8,48.96 32.53,48.69 v1(32.53,48.29) ; J6.13 v1(12.65,22.12) ; 100.02,11.79 100.07,11.79 100.38,12.09 100.38,12.7 98.41,14.67 v1(98.34,14.67) ; J6.16 v1(12.65,23.62) ; v1(12.49,48.21) 12.44,48.21 12.15,47.92 J2.10 ; J6.22 9.29,26.62 v1(9.14,26.77)
  TOP w0.381: U22.11 v1(18.49,60.98) ; C128.2 R158.1 v1(99.7,10.75) ; v1(72.61,9.25) 72.59,9.22 ; U26.39 87.5,51.18 87.09,51.59 v1(87.09,51.89) ; v1(41.75,50.48) 41.22,50.48 40.84,50.86 R243.1 ; U26.61 v1(68.35,57.1) ; U22.7 v1(22.09,60.98) ; v1(17.67,15.39) 16.56,15.39 16.29,15.66 16.29,16.93 16.56,17.2 17.11,17.2 C71.2 v1(17.15,18.05) 17.15,18.66 17.52,19.02 v1(18.63,19.02) Y3.4 ; v1(25.29,65.85) 25.29,66.19 25.09,66.39 J17.2 ; R195.1 99.73,30.86 v1(100.49,30.1) ; U26.52 v1(77.35,57.1) ; U26.L8 84.63,31.67 v1(84.68,31.62) ; U26.46 83.35,56.68 v1(83.77,57.1) ; J18.2 18.79,66.42 18.99,66.22 v1(18.99,65.85) ; J13.20 v1(62.96,64.99) ; v1(86.49,13.19) 86.49,12.17 86.35,12.03 U26.164 ; v1(69.57,60.2) 70.2,60.2 70.58,60.58 J13.25 ; J13.30 v1(75.66,68.97) ; U26.L46 51.69,14.71 v1(51.69,15.39) ; D7.1 81.92,8.64 v1(82.46,8.64) ; C152.2 v1(28.23,63.66) ; C178.2 39.85,26.73 39.85,24.84 39.47,24.46 C96.2 v1(39.7,23.95) ; v1(28.49,19.84) 28.37,19.71 28.37,18.93 ; R234.2 32.84,58.52 v1(33.24,58.12) ; R100.1 v1(28.5,30.23) ; Y2.4 v1(96.28,61.31) ; U22.3 v1(25.69,60.98) ; U26.21 v1(87.36,33.18) ; v1(33.73,32.72) 33.8,32.64 C93.2 ; U4.2 v1(38.32,31.09) ; v1(53.49,55.24) 53.35,55.38 U26.76 ; U26.67 62.35,55.26 v1(62.35,55.26) ; U18.2 v1(100.98,19.53) ; R194.2 v1(98.73,43.61) ; v1(32.74,41.58) 32.4,41.24 R12.2 ; S1.1 S2.2 v1(113.51,2.82) ; C64.2 v1(97,61.52) ; Y8.2 94.12,31.07 C137.1 v1(92.9,31.07) ; v1(30.72,48.5) v1(30.3,48.5) U22.39 ; U22.32 23.89,45.71 v1(24.28,46.1) ; R18.2 v1(36.84,27.55) ; U22.8 v1(21.19,60.98) ; R14.2 v1(35.12,47.96) ; U17.2 v1(100.98,15.93) ; v1(46.36,36.18) 45.35,36.18 U26.101 ; U26.32 87.18,44.18 86.76,43.76 86.76,42.49 v1(85.9,41.63) ; Y2.2 v1(99.69,58.41) ; S2.1 v1(117.36,2.63) ; S1.2 107.91,2.97 v1(107.58,2.65) ; J13.9 v1(50.26,63.59) ; D8.1 79.04,8.76 v1(79.48,9.21) ; v1(15.69,48.06) 15.69,48.12 16.07,48.5 U22.23 ; C92.2 35.1,27.07 v1(34.72,26.7) ; v1(106.42,59.56) 106.3,59.69 D12.1 ; v1(106.42,53.59) 106.24,53.41 D14.1 ; v1(30.07,25.53) 30.53,25.53 31.3,26.3 Y4.2 ; v1(29.1,65.3) 28.49,65.3 28.09,65.71 J17.3 ; C12.2 29.77,43.56 v1(29.33,43.56) ; C142.2 100.5,41.56 v1(100.79,41.27) ; D16.1 v1(101.76,54.03) ; v1(21.59,65.85) 21.59,66.32 21.79,66.52 J18.3 ; U26.149 71.35,11.18 71.35,9.57 v1(71.37,9.55) ; J13.34 v1(80.74,68.97) ; D13.1 v1(106.36,56.09) ; C146.1 98.84,30.57 98.46,30.19 ; v1(71.35,57.1) 71.35,57.1 U26.58 ; 98.46,30.19 v1(98.46,29.43) ; 98.46,30.19 Y8.4 ; U22.4 v1(24.79,60.98) ; D15.1 v1(101.76,51.35) ; Y7.2 94.53,12.35 C121.1 v1(92.97,11.44) ; R270.1 v1(100.11,60.82) ; U26.55 v1(74.35,57.1) ; U26.125 47.35,11.78 v1(46.91,12.22) ; Y3.2 21.18,16.03 21.81,16.03 22.45,16.66 v1(22.73,16.66) 22.45,16.94 C70.2 22.75,17.19 23.16,17.6 23.16,18.44 22.73,18.87 v1(22.42,18.87) ; U22.6 v1(22.99,60.98) ; C124.2 v1(93.36,24.61) ; U21.2 v1(100.98,39.16) ; 83.44,8.03 85.9,8.03 v1(86.06,7.86) ; D41.2 104.34,3.05 v1(105.1,3.05) 105.86,3.05 D39.2 ; C149.2 v1(21.93,63.66) ; C65.2 v1(94.74,60.02) ; U26.70 v1(59.35,55.26) ; R244.1 v1(31.87,54.38) ; U26.64 v1(65.35,54.76) ; U22.5 v1(23.89,60.98) ; U22.1 v1(27.49,60.98) ; R19.2 v1(35.09,30.14) ; D34.1 v1(21.93,64.51) ; J13.14 v1(55.34,64.99) ; J13.6 v1(45.17,68.97) ; U26.73 v1(56.35,55.26) ; U26.115 v1(44.34,22.18) ; 60.35,9.88 U26.138 ; J13.39 v1(88.36,59.61) ; D11.1 v1(106.36,57.01) ; U20.2 v1(100.98,35.56) ; D35.1 v1(28.23,64.51) ; U26.49 v1(80.35,57.1) ; U22.10 v1(19.39,60.98)
  TOP w0.635: MTG6.1 93.22,67.65 ; MTG6.1 89.86,64.29 ; MTG6.1 93.22,60.94 ; MTG6.1 96.57,64.29 ; MTG5.1 35.22,67.65 ; MTG5.1 35.22,60.94 ; MTG5.1 38.57,64.29 ; MTG5.1 31.86,64.29
  GND02 w0.635: 93.22,60.94 MTG6.1 ; MTG6.1 96.57,64.29 ; MTG6.1 93.22,67.65 ; MTG6.1 89.86,64.29 ; 35.22,60.94 MTG5.1 ; MTG5.1 31.86,64.29 ; MTG5.1 38.57,64.29 ; MTG5.1 35.22,67.65
  ART03 w0.152: 25.55,42.01 25.55,44.42 26.21,45.09 28.47,45.09 30.27,46.89 30.27,47.55 30.48,47.75 31.01,47.75 31.29,48.03 31.44,48.03 31.7,48.29 v1(32.53,48.29) 32.53,48.44 32.8,48.7 33.52,48.7 33.68,48.86 33.68,49.5 33.85,49.68 34.87,49.68 35.45,50.27 35.66,50.27 36.11,50.72 v1(36.24,50.72) 36.24,51.03 35.78,51.49 32.25,51.49 31.51,50.74 31.51,49.29 v1(30.72,48.5) v1(30.3,48.5) 28.58,48.5 28.29,48.21 28.29,46.2 28.01,45.92 27.63,45.92 27.12,46.43 26.59,46.43 24.84,44.68 24.84,43.64 24.53,43.33 24.05,43.33 v1(23.8,43.59)
  ART03 w0.635: MTG6.1 93.22,67.65 ; MTG6.1 93.22,60.94 ; MTG6.1 96.57,64.29
  ART04 w0.152: 56.84,13.26 45.97,13.26 45.13,14.1 44.09,14.1 43.76,14.43 43.76,16.69 43.3,17.14 41.14,17.14 39.77,18.52 39.77,22 39.39,22.38 39.39,23.64 v1(39.7,23.95) 39.42,24.24 39.42,25.32 38.78,25.96 38.78,26.57 39.01,26.8 39.42,26.8 39.62,27 39.62,30.38 39.21,30.78 v1(39.21,31.11) 39.21,31.8 38.38,32.64 38.38,36.83 36.78,38.43 36.78,44.2 36.19,44.78 36.19,45.42 36.34,45.57 36.78,45.57 37.16,45.95 37.16,47.27 36.47,47.96 v1(35.12,47.96) 35.02,48.05 35.02,49.12 35.45,49.56 36.32,49.56 36.67,49.91 36.67,50.34 36.29,50.72 v1(36.24,50.72) 36.09,50.72 35.86,50.5 34.72,50.5 34.36,50.14 34.36,46.53 34.51,46.38 35.05,46.38 35.23,46.2 35.23,38.99 37.28,36.93 37.28,32.13 v1(38.32,31.09) 38.05,30.81 38.05,24.89 38.58,24.36 38.58,22.12 39.09,21.62 39.09,17.9 43.53,13.46 44.7,13.46 45.94,12.22 v1(46.91,12.22) 50.77,12.22 51.08,12.52 52.26,12.52 v1(52.77,12.01) 53.21,12.45 55.32,12.45 v1(55.85,11.91) 56.1,11.66 67.59,11.66 67.84,11.4 76.04,11.4 77.97,13.34 79.93,13.34 80.79,12.47 v1(81.43,12.47) v1(82.19,12.47) v1(82.95,12.47) 84.2,12.47 84.6,12.88 86.18,12.88 v1(86.49,13.19) 87.22,13.92 87.22,14.68 87.02,14.88 86.64,14.88 85.34,13.59 84.02,13.59 83.79,13.36 v1(82.95,13.36) v1(82.19,13.36) v1(81.43,13.36) 80.77,13.36 80.08,14.05 77.57,14.05 v1(77.39,13.86) 75.56,12.04 68.65,12.04 67.81,12.88
  ART04 w0.635: 89.86,64.29 MTG6.1 ; MTG6.1 93.22,60.94 ; MTG6.1 96.57,64.29 ; MTG6.1 93.22,67.65
  POW05 w0.635: MTG6.1 93.22,67.65 ; MTG6.1 89.86,64.29 ; MTG6.1 93.22,60.94 ; MTG6.1 96.57,64.29
  BOTTOM w0.152: 31.52,45.36 31.52,43.97 31.16,43.61 29.38,43.61 v1(29.33,43.56) 29.33,43.54 28.85,43.05 24.33,43.05 v1(23.8,43.59) 23.54,43.84 22.42,43.84 v1(22.02,43.43) 22.02,43.61 21.64,43.99 19.63,43.99 18.31,45.31 18.31,46.61 18.46,46.76 18.61,46.76 v1(18.74,46.89) ; v1(19.73,51.31) 19.73,50.88 20.09,50.52 20.09,49.63 19.73,49.28 19.73,46.51 20.11,46.13 21.87,46.13 22.27,45.72 23.64,45.72 25.6,43.76 28.39,43.76 29.23,44.6 30.35,44.6 30.55,44.81 30.55,45.14
  BOTTOM w0.203: C60.2 94.57,57.47 v1(94.36,57.68) ; R45.2 77.64,11.2 77.44,11 77.44,8.36 v1(77.09,8) v1(76.66,8) ; C66.2 9.66,58.89 v1(10.16,58.39) 10.36,58.19 v1(10.36,57.84) ; v1(82.19,12.47) 81.94,12.22 U9.22 ; J5.10 12.3,56.88 v1(10.89,56.88) ; U8.2 v1(47.6,24.1) ; J5.11 27.2,56.83 v1(26.06,56.83) ; v1(85.99,32.97) R167.2 R168.2 ; v1(85.99,32.97) 85.99,34.17 v1(86.1,34.29) ; v1(85.99,32.97) 87.15,32.97 v1(87.36,33.18) ; v1(27.12,51.89) 27.56,51.46 R222.1 27.56,51.06 27.28,50.77 27.28,50.01 v1(26.77,49.5) ; R209.2 85.07,45.18 85.44,44.81 85.72,44.81 v1(85.75,44.78) ; D43.1 8.56,16.94 v1(8.76,16.74) ; 72.01,9.4 72.01,9.4 ; D19.1 30.48,55.28 v1(30.48,55.68) ; D23.1 12.92,54.91 v1(13.09,55.08) ; R168.2 v1(85.2,31.18) ; R168.2 R169.2 v1(85.99,29.3) ; D24.1 9.17,54.16 v1(8.93,53.92) ; v1(17.65,51.23) 17.65,50.85 18.11,50.39 18.11,47.52 v1(18.74,46.89) ; v1(82.46,8.64) 82.52,8.64 82.8,8.36 82.8,7.75 82.05,7 D10.1 ; C63.2 v1(93.62,52.35) ; v1(20.7,5.66) 20.85,5.51 U14.2 ; D18.1 v1(30.86,57.9) ; v1(32.53,48.29) 32.04,48.29 R246.1 30.76,48.46 v1(30.72,48.5) v1(30.3,48.5) 29.75,48.5 29.27,48.01 C155.2 C153.2 ; J5.12 v1(12.55,67.77) ; v1(82.19,13.36) 82.44,13.61 U9.10 ; v1(24.96,46.79) C154.2 ; R171.2 88.37,26.42 88.03,26.09 87.45,26.09 v1(87.37,26.01) ; 30.28,13.25 31.77,13.25 ; C62.2 97.47,52.92 v1(96.9,53.49) ; v1(8.28,46.43) 7.99,46.72 Y1.2 7.99,48.2 v1(8.25,48.46) ; v1(61.86,60.69) C160.2 v1(61.86,62.52) ; v1(9.11,39.75) 9.11,39.85 ; v1(10.49,62.64) 10.46,62.66 v1(9.66,62.66) C67.2 ; C172.2 46.41,58.6 47.14,58.6 48.61,57.12 48.61,56.39 ; R48.2 v1(86.91,55.26) ; C113.2 v1(90.04,11.55)
  BOTTOM w0.254: U23.8 33.42,54.1 v1(33.45,54.13)
  BOTTOM w0.305: v1(20.47,30.58) 20.47,30.71 20.85,31.09 v1(21.99,31.09) ; v1(21.28,49.78) v1(21.28,51.26) 23.03,53.01 v1(23.97,53.01) 24.81,53.01 25.73,52.09 Y9.2 26.93,52.09 v1(27.12,51.89)
  BOTTOM w0.381: v1(59.71,15.37) 60,15.08 Y6.2 ; v1(85.14,46.91) 85.4,47.18 R204.2 R205.2 ; D22.1 15.66,54.69 v1(15.4,54.95) ; R210.2 C134.2 C133.2 93.09,30.89 v1(92.9,31.07) ; D30.1 v1(98.55,9.07) ; v1(17.9,30.3) 17.89,30.32 C73.2 ; v1(85.31,42.04) 85.07,42.28 R208.2 ; C49.2 v1(86.06,7.86) ; C138.2 86.1,38.49 86.1,39.2 v1(86.17,39.27) ; C126.2 96.88,18.24 96.5,17.86 v1(95.88,17.86) ; v1(99.7,10.75) 100.21,11.26 D31.1 ; R9.1 v1(68.71,13.46) ; v1(52.77,12.01) 52.17,12.01 C109.2 ; C37.2 49,25.87 v1(49.07,25.93) C38.2 ; v1(9.88,30.62) 13.35,30.62 13.88,31.16 D45.1 ; v1(98.24,12.8) 97.89,12.45 R166.2 ; R207.2 87.68,50.22 87.3,49.83 85.89,49.83 85.68,49.63 R206.2 R205.2 ; C174.2 45.71,48.94 C173.2 v1(47.79,48.94) ; v1(21.28,51.26) 21.23,51.31 v1(19.73,51.31) ; v1(17.73,57.76) 17.05,57.08 J5.6 ; v1(98.46,29.43) 98.21,29.68 R202.2 ; C145.2 97.9,33.67 98.37,33.2 v1(99.23,33.2) ; C75.2 23.44,22.91 v1(23.41,22.89) 22.89,22.36 C77.2 ; v1(82.46,8.64) 82.06,8.64 81.57,9.13 C50.2 ; R165.2 95.51,11.38 96.55,10.34 98.57,10.34 v1(98.67,10.44) ; D2.1 66.74,6.92 D5.1 D4.1 ; v1(96.11,50.77) 96.48,50.41 C56.2 ; C130.2 94.86,19.78 v1(94.86,18.87) ; v1(93.84,17.86) 93.43,18.28 C117.2 ; C74.2 21.46,28.98 v1(21.99,29.51) ; v1(85.75,40.67) 85.63,40.55 C139.2 ; v1(53.46,15.37) 53.21,15.11 Y5.2 52.53,15.08 51.99,15.08 v1(51.69,15.39) ; R63.2 v1(102.24,9.22) ; D37.1 v1(107.58,2.65) ; R203.2 v1(100.49,30.1) ; U25.11 v1(83.93,64.15) ; C118.2 v1(89.59,17.84) ; D21.1 v1(18.34,54.71) 18.97,54.71 18.97,54.71 19.35,54.71 D20.1 ; v1(24.53,38.11) 24.97,38.11 25.35,37.73 C34.2 ; v1(18.87,12.09) 18.17,11.4 R105.2 ; v1(21.31,35.05) 21.03,34.77 21.03,34.26 C36.2 ; v1(95.5,50.77) 95.13,50.41 C57.2 94.55,50.41 93.98,50.98 v1(93.98,51.54) ; U25.8 v1(79.59,67.96) ; C164.2 v1(116.71,5.92) ; v1(8.96,23.47) 8.38,24.05 D44.1 ; v1(20.93,20.35) 20.56,20.71 C89.2 ; C144.2 96.14,37.76 v1(95.88,37.49) ; C78.2 v1(23.26,29.54) ; v1(100.79,41.27) 101.22,41.27 C140.2 C141.2 v1(101.5,43.1) ; v1(74.5,64.15) U25.4 v1(77.32,64.15) ; C29.2 12.8,41.84 v1(12.8,39.55) ; R62.2 101.45,2.79 101.83,2.41 104.47,2.41 v1(105.1,3.05) ; C33.2 25.19,32.9 v1(24.18,33.92) ; C135.2 96.32,38.96 v1(95.88,38.51) ; D9.1 79.2,5.95 77.75,4.5 v1(77.75,4.32) ; v1(95.88,16.84) 95.96,16.76 C125.2 ; v1(23.17,48.55) C158.2 R233.2 ; 9.11,39.85 9.69,40.43 C30.2 ; C91.2 v1(18.16,7.21) ; D4.1 v1(65.41,6.38) ; D4.1 64.83,6.92 64.51,7.24 D3.1 ; C111.2 59.87,10.66 ; R205.2 85.5,48.18 85.34,48.34 v1(85.16,48.34) ; D38.1 v1(114.47,2.96) ; v1(95.88,36.48) 96.6,35.76 C143.2 C136.2 ; v1(21.13,8.48) 21.48,8.84 21.48,9.78 20.95,10.31 R106.2 ; v1(93.84,38.51) 93.73,38.62 C148.2 ; C159.2 v1(108.89,6.78) ; C112.2 56.23,12.49 55.85,12.11 v1(55.85,11.91) ; v1(91.39,21.74) 90.92,21.28 C131.2 ; v1(87.37,26.01) 87.27,26.01 86.37,25.11 R172.2 ; U25.14 v1(84.2,60.34) ; R49.2 v1(86.49,13.19) ; C40.2 v1(48.37,18.35) ; C120.2 v1(101.97,12.78) ; D46.1 13.74,36.85 v1(13.74,37.24) ; D33.1 v1(100.87,28.18) ; C119.2 96.38,19.96 95.88,19.45 v1(95.88,18.87) ; C157.2 v1(20.21,47.79) ; C59.2 v1(98.32,47.6) ; v1(20.54,38.11) 20.13,38.11 19.75,37.73 C35.2 ; R52.2 77.99,13.87 C48.2 v1(77.39,13.86) ; C110.2 48.72,12.28 48.21,11.76 47.37,11.76 v1(46.91,12.22) ; R64.2 93.26,6.32 R65.2 v1(93.25,7.97) ; v1(37.58,21.54) 37.58,21.59 37.73,21.75 R120.1 ; R245.1 v1(41.75,50.48) ; C47.2 79.42,9.27 v1(79.48,9.21) ; v1(92.97,11.44) 92.85,11.56 R173.2 ; J5.13 v1(29.76,66.43) ; C80.2 21.58,22.69 v1(21.38,22.89) ; v1(75.66,68.97) 75.61,69.02 R255.1 ; C85.2 v1(17.19,21.17) ; C39.2 v1(46.39,18.64) ; C129.2 100.58,19.13 v1(100.98,19.53) ; C123.2 v1(90,15.3) ; D32.1 v1(100.87,27.38) ; C90.2 v1(22.07,7.21) ; C58.2 v1(98.32,46.69) ; C127.2 v1(98.34,14.67) ; 72.01,9.4 C13.2 ; R170.2 v1(90.09,28.41) ; U25.9 v1(79.59,66.69)
  BOTTOM w0.635: MTG6.1 96.57,64.29 ; MTG6.1 93.22,60.94 ; MTG6.1 93.22,67.65 ; MTG6.1 89.86,64.29
  vias: v1(8.17,49.15) v1(8.23,39.75) v1(8.23,39.32) v1(8.23,38.89) v1(8.25,50.19) v1(8.38,55.98) v1(8.39,55.46) v1(8.66,39.75) v1(8.66,39.32) v1(8.66,38.89) v1(9.14,55.98) v1(9.11,39.32) v1(9.11,38.89) v1(9.95,14.76) v1(9.95,13.74) v1(10.74,10.46) v1(10.77,10.95) v1(10.77,9.93) v1(10.77,9.42) v1(10.77,8.94) v1(10.77,8.46) v1(10.97,14.76) v1(10.97,13.74) v1(12.65,14.76) v1(13.41,14.76) v1(13.71,59.69) v1(13.84,51) v1(14.09,51.46) v1(14.63,48.56) v1(14.93,68.86) v1(15.01,59.36) v1(14.96,42.27) v1(14.96,41.76) v1(14.96,41.25) v1(15.46,42.27) v1(15.46,41.76) v1(15.46,41.25) v1(15.77,64.24) v1(16.46,67.92) v1(18.23,65.18) v1(18.33,62.81) v1(18.51,63.7) v1(18.84,61.9) v1(19.35,23.9) v1(19.35,22.89) v1(20.37,26.95) v1(20.37,25.93) v1(20.37,24.92) v1(20.37,23.9) v1(20.37,22.89) v1(20.44,14.53) v1(21.38,26.95) v1(21.38,25.93) v1(21.38,24.92) v1(21.38,23.9) v1(21.54,61.9) v1(21.81,14.45) v1(22.27,62.28) v1(22.4,25.93) v1(22.4,24.92) v1(22.4,23.9) v1(22.4,22.89) v1(23.14,14.48) v1(23.26,65.05) v1(23.44,62.13) v1(23.41,25.93) v1(23.41,24.92) v1(23.64,63.65) v1(24.51,62.36) v1(24.71,64.62) v1(25.52,63.8) v1(25.5,62.81) v1(25.6,13.08) v1(26.06,52.98) v1(26.08,13.08) v1(26.56,13.08) v1(27.07,13.08) v1(28.83,62.36) v1(29.54,30.94) v1(29.61,33.43) v1(29.79,28.98) v1(29.92,20.04) v1(29.87,18.03) v1(29.99,27.33) v1(30.02,21.87) v1(30.1,23.7) v1(31.14,17.87) v1(31.93,36.55) v1(31.93,36.12) v1(31.93,35.69) v1(31.9,24.92) v1(32.39,36.55) v1(32.39,36.12) v1(32.39,35.69) v1(32.38,4.57) v1(32.38,4.14) v1(32.38,3.68) v1(32.46,13.67) v1(32.81,4.57) v1(32.81,4.14) v1(32.81,3.68) v1(32.99,12.67) v1(33.24,4.57) v1(33.24,4.14) v1(33.24,3.68) v1(33.67,4.57) v1(33.67,4.14) v1(33.67,3.68) v1(33.83,12.7) v1(33.91,45.72) v1(33.96,43.72) v1(33.96,43.28) v1(34.31,34.82) v1(34.31,34.37) v1(34.34,23.7) v1(34.41,43.72) v1(34.41,43.28) v1(34.74,55.91) v1(34.74,55.5) v1(34.74,34.82) v1(34.74,34.37) v1(34.92,36.2) v1(34.92,35.74) v1(35.15,55.91) v1(35.15,55.5) v1(35.15,23.88) v1(35.18,34.82) v1(35.18,34.37) v1(35.23,22.66) v1(35.35,36.2) v1(35.35,35.74) v1(35.4,26.49) v1(35.48,5.16) v1(35.56,55.91) v1(35.56,55.5) v1(35.78,36.2) v1(35.78,35.74) v1(36.81,21.54) v1(36.81,20.07) v1(37.58,20.83) v1(37.58,20.07) v1(38.26,20.83) v1(38.26,20.07) v1(40.1,31.06) v1(40.64,69.24) v1(41.04,69.24) v1(41.04,68.83) v1(40.97,62.69) v1(41.45,69.24) v1(41.45,68.83) v1(41.37,62.69) v1(41.78,62.69) v1(41.86,69.24) v1(42.06,54.79) v1(42.06,54.38) v1(42.06,53.98) v1(42.46,54.79) v1(42.46,54.38) v1(42.46,53.98) v1(43.4,42.72) v1(43.4,42.29) v1(43.4,41.83) v1(43.83,42.72) v1(43.83,42.29) v1(43.83,41.83) v1(46.78,3.68) v1(46.78,3.25) v1(46.78,2.79) v1(47.21,3.68) v1(47.21,3.25) v1(47.21,2.79) v1(47.64,3.68) v1(47.64,3.25) v1(47.64,2.79) v1(47.7,69.11) v1(47.8,50.55) v1(48,50.9) v1(49.83,55.4) v1(51,53.47) v1(51.35,53.72) v1(51.79,53.77) v1(52.07,69.04) v1(52.19,53.77) v1(53.92,53.59) v1(54.91,10.41) v1(55.04,69.01) v1(55.83,53.59) v1(56.92,69.01) v1(57.3,53.37) v1(57.91,9.32) v1(58.11,10.26) v1(58.44,52.07) v1(59.86,53.44) v1(60.95,10.36) v1(61.21,53.42) v1(61.36,9.45) v1(62.96,54.97) v1(64,12.58) v1(64.43,12.56) v1(64.77,54.97) v1(65.83,10.49) v1(65.88,58.06) v1(67.74,58.01) v1(70.91,9.55) v1(70.94,9.07) v1(71.4,9.07) v1(71.52,65.74) v1(71.52,65.33) v1(71.93,65.74) v1(71.93,65.33) v1(71.88,54.46) v1(72.61,8.79) v1(73.1,9.27) v1(73.1,8.81) v1(73.53,9.3) v1(73.53,8.84) v1(73.76,54.46) v1(74.82,9.3) v1(74.82,8.79) v1(75.15,54.41) v1(75.38,9.3) v1(75.38,8.79) v1(76.5,54.41) v1(78,55.17) v1(77.97,53.37) v1(79.32,68.88) v1(85.57,20.98) v1(85.75,23.39) v1(87.75,68.96) v1(88.39,4.83) v1(88.41,4.42) v1(88.79,4.85) v1(88.82,4.45) v1(89.2,4.85) v1(89.23,4.45) v1(89.61,11.56) v1(92.93,68.99) v1(93.24,55.6) v1(93.26,57.43) v1(93.62,28.5) v1(93.62,27.84) v1(93.84,37.49) v1(93.84,36.48) v1(93.84,18.87) v1(93.84,16.84) v1(94.71,68.66) v1(94.86,38.51) v1(94.86,37.49) v1(94.86,36.48) v1(94.86,17.86) v1(94.86,16.84) v1(95.8,67.59) v1(95.88,55.52) v1(95.88,54.51) v1(95.88,53.49) v1(96.9,55.52) v1(96.9,54.51) v1(97.91,55.52) v1(97.91,54.51) v1(97.91,53.49) v1(98.62,48.21) v1(98.68,63.45) v1(99.21,57.48) v1(100.73,62) v1(100.73,61.49) v1(100.73,60.99) v1(101.24,62) v1(101.24,61.49) v1(101.24,60.99) v1(102.05,50.27) v1(102.05,49.76) v1(102.05,49.25) v1(102.56,50.27) v1(102.56,49.76) v1(102.56,49.25) v1(102.87,23.93) v1(102.87,23.47) v1(103.88,63.45) v1(106.75,64.44) v1(107.97,64.44) v1(109.42,64.44) v1(110.79,64.44)
GND_EARTH: length 96.4
  TOP w0.381: v1(72.31,2.99) 72.28,2.97 ; 10.89,3.63 MTG4.6
  GND02 w0.635: 121.5,1.5 MTG3.9 ; MTG3.9 119.5,3.5 ; MTG3.9 121.5,5.5 ; MTG3.9 123.5,3.5 ; 6.5,66.5 MTG1.9 ; MTG1.9 8.5,68.5 ; MTG1.9 10.5,66.5 ; MTG1.9 8.5,64.5 ; MTG2.9 123.5,66.5 ; MTG2.9 121.5,64.5 ; MTG2.9 119.5,66.5 ; MTG2.9 121.5,68.5
  ART03 w0.635: 119.5,3.5 MTG3.9 ; MTG3.9 123.5,3.5 ; MTG3.9 121.5,1.5 ; MTG3.9 121.5,5.5 ; 6.5,66.5 MTG1.9 ; MTG1.9 8.5,68.5 ; MTG1.9 10.5,66.5 ; MTG1.9 8.5,64.5 ; 121.5,64.5 MTG2.9 ; MTG2.9 121.5,68.5 ; MTG2.9 123.5,66.5 ; MTG2.9 119.5,66.5
  ART04 w0.635: 119.5,66.5 MTG2.9 ; MTG2.9 121.5,68.5 ; MTG2.9 123.5,66.5 ; MTG2.9 121.5,64.5 ; MTG1.9 10.5,66.5 ; MTG1.9 8.5,64.5 ; MTG1.9 8.5,68.5 ; MTG1.9 6.5,66.5 ; MTG3.9 123.5,3.5 ; MTG3.9 119.5,3.5 ; MTG3.9 121.5,1.5 ; MTG3.9 121.5,5.5
  POW05 w0.635: MTG2.9 121.5,68.5 ; MTG2.9 121.5,64.5 ; MTG2.9 119.5,66.5 ; MTG2.9 123.5,66.5 ; 119.5,3.5 MTG3.9 ; MTG3.9 121.5,5.5 ; MTG3.9 121.5,1.5 ; MTG3.9 123.5,3.5 ; 6.5,66.5 MTG1.9 ; MTG1.9 10.5,66.5 ; MTG1.9 8.5,64.5 ; MTG1.9 8.5,68.5
  vias: v1(5.74,68.78) v1(5.74,64.24) v1(5.74,60.43) v1(5.74,56.62) v1(5.74,52.81) v1(5.74,49) v1(5.74,45.19) v1(5.74,41.38) v1(5.74,37.57) v1(5.74,33.76) v1(5.74,29.95) v1(5.74,26.14) v1(5.74,22.33) v1(5.74,18.52) v1(5.74,14.71) v1(5.74,10.9) v1(5.74,7.09) v1(6.4,0.84) v1(13.03,0.79) v1(16.84,0.79) v1(20.65,0.79) v1(24.46,0.79) v1(28.27,0.79) v1(32.08,0.79) v1(35.89,0.79) v1(39.7,0.79) v1(43.51,0.79) v1(47.32,0.79) v1(51.13,0.79) v1(53.01,0.81) v1(58.75,0.79) v1(62.56,0.79) v1(66.37,0.79) v1(70.18,0.79) v1(72.31,2.54) v1(72.79,3.02) v1(72.79,2.56) v1(73.22,3.04) v1(73.22,2.59) v1(73.99,0.79) v1(77.8,0.79) v1(81.61,0.79) v1(85.77,0.79) v1(89.23,0.79) v1(93.04,0.79) v1(96.85,0.79) v1(100.66,0.79) v1(104.47,0.79) v1(106.27,62.31) v1(106.27,61.8) v1(106.27,61.29) v1(106.78,62.31) v1(106.78,61.8) v1(106.78,61.29) v1(108.28,0.79) v1(112.09,0.79) v1(115.9,0.79) v1(119.71,0.79) v1(124.13,0.81) v1(124.2,62.94) v1(124.2,59.13) v1(124.2,55.32) v1(124.2,51.51) v1(124.2,47.7) v1(124.2,43.89) v1(124.2,40.08) v1(124.2,36.27) v1(124.2,32.46) v1(124.2,28.65) v1(124.2,24.84) v1(124.2,21.03) v1(124.2,17.22) v1(124.2,13.41) v1(124.2,9.6) v1(124.2,5.79)
VDD_1V8: length 80.1
  TOP w0.381: v1(15.97,32.61) 16.14,32.45 R31.1 R26.1 ; R29.1 16.74,34.65 17.21,35.12 R28.1 ; R29.1 R30.1 ; R29.1 v1(16.06,34.23) ; C24.2 R17.2 35.09,33.39 v1(35.1,33.4) ; v1(49.63,19) 49.5,18.87 48.43,18.87 46.42,20.88 v1(46.42,24.28) ; v1(24.81,8.66) 25.19,9.04 25.19,12.22 24.94,12.47 24.94,15.94 R76.1 26.68,16.78 v1(27.91,18.01) ; U7.2 v1(21.61,36.67)
  ART03 w0.381: 43.33,33.73 45.06,32 45.06,25.65 v1(46.42,24.28) ; v1(20.47,48.68) 19.9,48.68 19.33,48.11 17.6,48.11 16.28,46.79 14.47,46.79 12.29,44.6 v1(12.21,44.6)
  ART04 w0.381: 24.86,28.4 24.86,20.98 27.83,18.01 v1(27.91,18.01)
  BOTTOM w0.203: U8.3 48.1,24.51 C38.1
  BOTTOM w0.381: R230.1 v1(20.47,48.68) ; v1(24.81,8.66) 24.81,9.35 23.92,10.24 Q5.3 ; 37.92,33.91 37.41,33.4 v1(35.1,33.4) ; v1(21.61,36.67) 20.77,36.67 C35.1 19.75,34.5 C36.1 ; v1(46.42,24.28) C37.1 46.43,24.99 C38.1 ; v1(12.21,44.6) 12.21,44.5 12.47,44.25 FB1.2 12.47,43.31 13.69,42.09 v1(13.69,40.69) v1(13.69,40.21) ; R34.1 49.48,19.15 v1(49.63,19)
  vias: v1(15.77,29.91) v1(15.79,29.34) v1(16.12,29.63) v1(16.66,37.8) v1(17.06,37.78) v1(24.23,30.53) v1(24.23,30.12) v1(24.66,30.53) v1(24.66,30.12) v1(26.92,36.6) v1(27.33,36.6) v1(27.73,36.58) v1(28.14,36.58) v1(28.42,36.27) v1(42.97,35.18) v1(42.97,34.75) v1(42.97,34.31) v1(43.43,35.18) v1(43.43,34.75) v1(43.43,34.31)
